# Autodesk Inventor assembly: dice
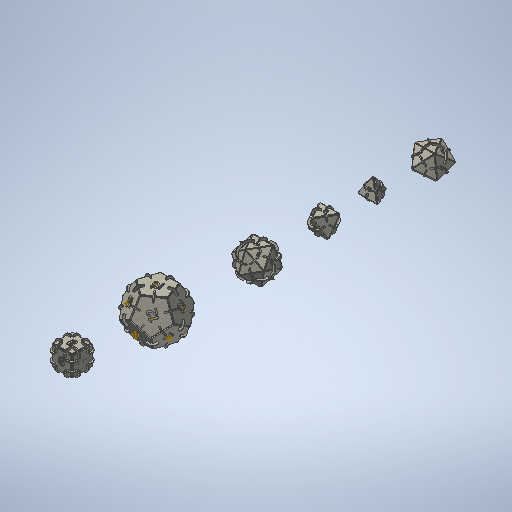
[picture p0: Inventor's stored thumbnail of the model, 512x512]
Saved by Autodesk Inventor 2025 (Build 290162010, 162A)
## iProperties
Created: 2025-02
Part Number: dice
Material: Generisch
Document SubType Name: Assembly
Designer: BennF
Author: BennF
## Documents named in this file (7)
- C:\Users\BennF\OneDrive - Technische Universität Ilmenau\FabAcademy\week03\dice.iam
- C:\Users\BennF\OneDrive - Technische Universität Ilmenau\FabAcademy\week03\cube.iam
- C:\Users\BennF\OneDrive - Technische Universität Ilmenau\FabAcademy\week03\dodecahedron.iam
- C:\Users\BennF\OneDrive - Technische Universität Ilmenau\FabAcademy\week03\Icosahedron.iam
- C:\Users\BennF\OneDrive - Technische Universität Ilmenau\FabAcademy\week03\octahedron.iam
- C:\Users\BennF\OneDrive - Technische Universität Ilmenau\FabAcademy\week03\tetrahedron.iam
- C:\Users\BennF\OneDrive - Technische Universität Ilmenau\FabAcademy\week03\trigonal_dodecahedron.iam
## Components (6 placed, 6 different names)
1. cube:1 [sub-assembly]
2. dodecahedron:1 [sub-assembly]
3. Icosahedron:1 [sub-assembly]
4. octahedron:1 [sub-assembly]
5. tetrahedron:1 [sub-assembly]
6. trigonal_dodecahedron:1 [sub-assembly]
